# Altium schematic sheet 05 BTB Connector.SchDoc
size 594 x 420 mm
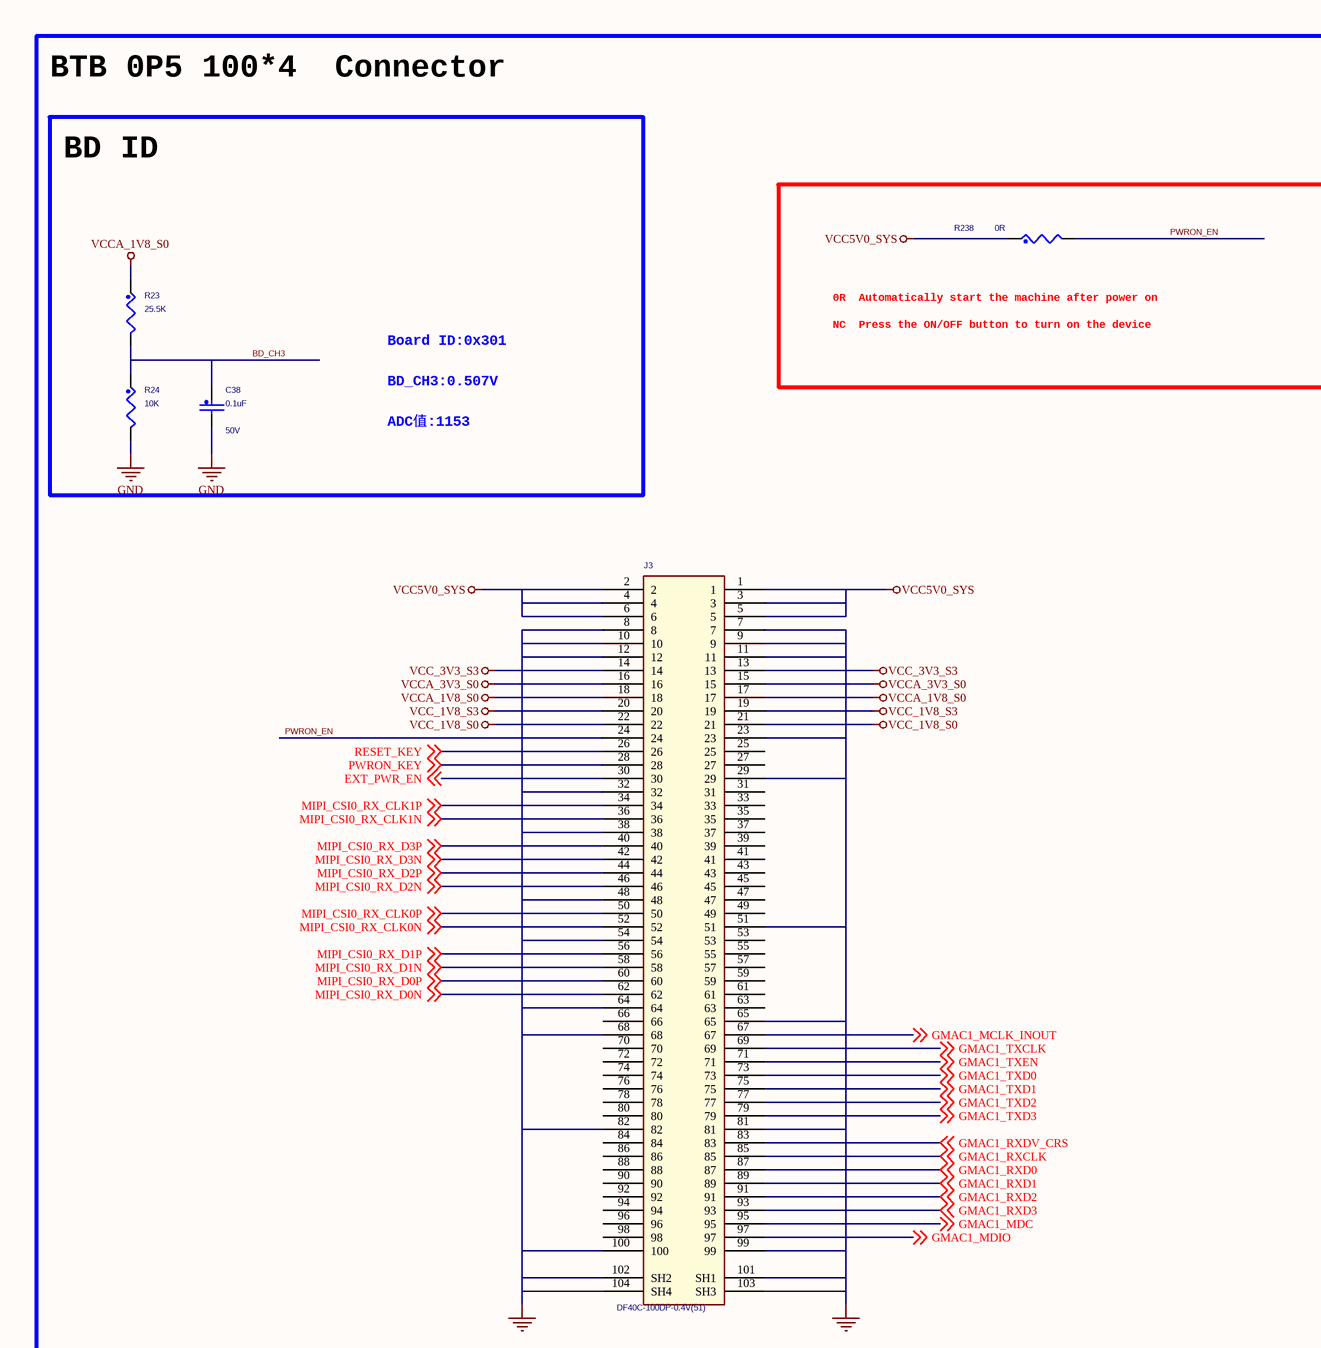
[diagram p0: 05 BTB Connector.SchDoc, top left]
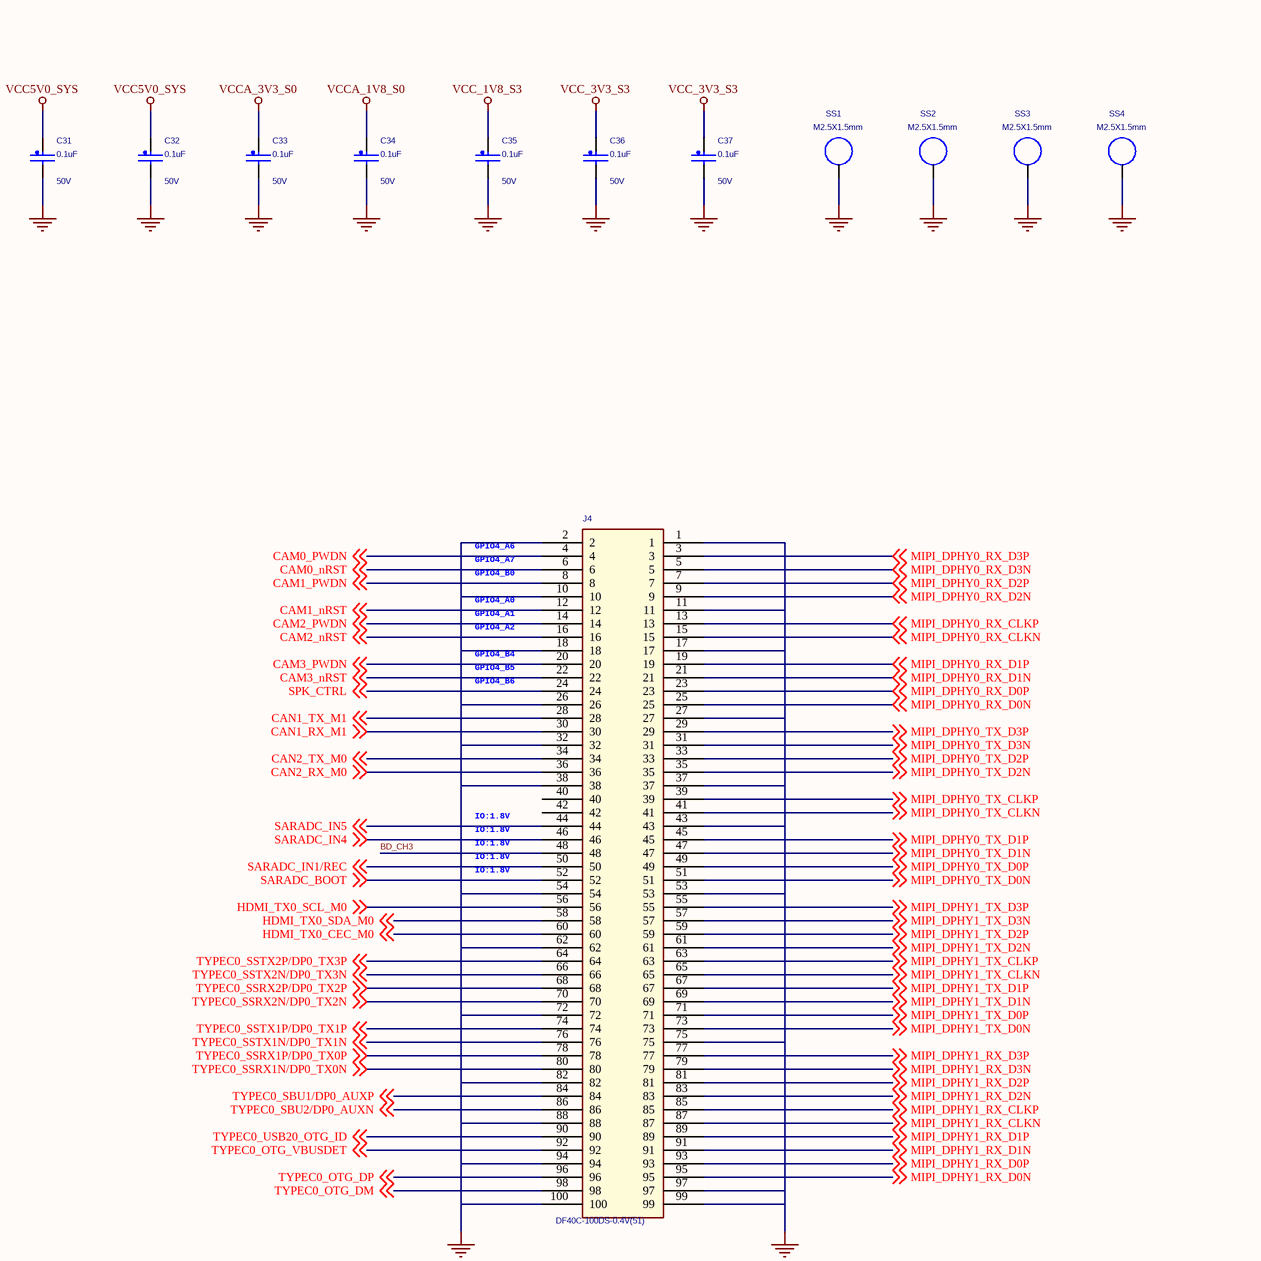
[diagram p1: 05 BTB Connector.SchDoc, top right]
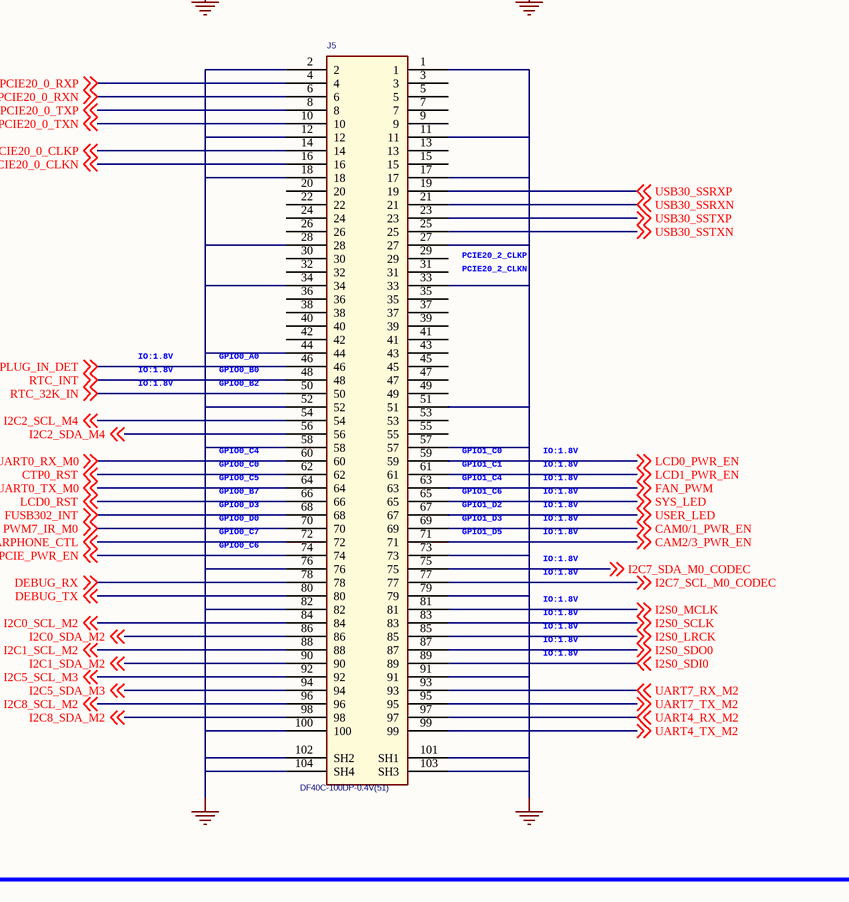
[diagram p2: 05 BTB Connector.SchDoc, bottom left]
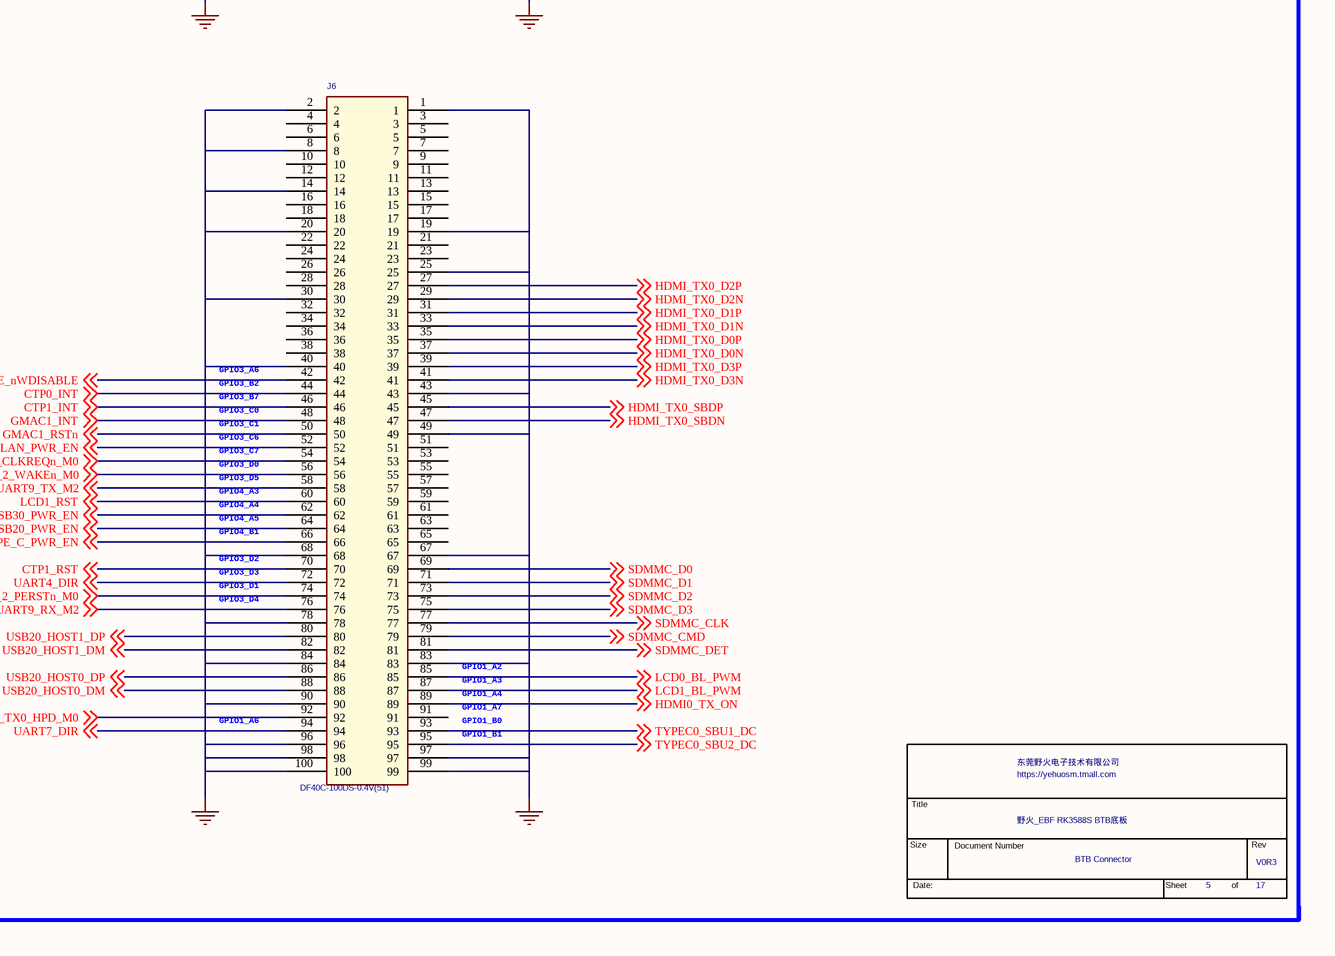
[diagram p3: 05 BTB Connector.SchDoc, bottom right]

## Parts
*  Page Count: 17  Page Number: 5  OrgName: 东莞野火电子技术有限公司  Title: 野火_EBF RK3588S BTB底板  RevCode: V0R3  Doc: BTB Connector  (hidden comment: TitleBlock_YHSCH)  (graphical)
C31  0.1uF  Voltage: 50V  [C0402]
C32  0.1uF  Voltage: 50V  [C0402]
C33  0.1uF  Voltage: 50V  [C0402]
C34  0.1uF  Voltage: 50V  [C0402]
C35  0.1uF  Voltage: 50V  [C0402]
C36  0.1uF  Voltage: 50V  [C0402]
C37  0.1uF  Voltage: 50V  [C0402]
C38  0.1uF  Voltage: 50V  [C0402]
J3  DF40C-100DP-0.4V(51)  [DF40C-100DP-0P4V]
J4  DF40C-100DS-0.4V(51)  [DF40HC-100DS-0P4V]
J5  DF40C-100DP-0.4V(51)  [DF40C-100DP-0P4V]
J6  DF40C-100DS-0.4V(51)  [DF40HC-100DS-0P4V]
R23  25.5K  [R0402]
R24  10K  [R0402]
R238  0R  [R0402]
SS1  M2.5X1.5mm  [SMTSO-M2r5]
SS2  M2.5X1.5mm  [SMTSO-M2r5]
SS3  M2.5X1.5mm  [SMTSO-M2r5]
SS4  M2.5X1.5mm  [SMTSO-M2r5]

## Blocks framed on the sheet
BD ID: C38 R23 R24

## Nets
GND: C31.2 C32.2 C33.2 C34.2 C35.2 C36.2 C37.2 C38.2 J3.7 J3.8 J3.9 J3.10 J3.11 J3.12 J3.23 J3.29 J3.32 J3.38 J3.48 J3.51 J3.54 J3.64 J3.65 J3.68 J3.81 J3.82 J3.99 J3.100 J3.101(SH1) J3.102(SH2) J3.103(SH3) J3.104(SH4) J4.1 J4.2 J4.10 J4.11 J4.17 J4.18 J4.26 J4.27 J4.32 J4.37 J4.38 J4.43 J4.53 J4.54 J4.62 J4.72 J4.75 J4.82 J4.88 J4.94 J4.97 J4.99 J4.100 J5.1 J5.2 J5.11 J5.12 J5.17 J5.18 J5.27 J5.28 J5.33 J5.34 J5.44 J5.51 J5.52 J5.57 J5.58 J5.73 J5.76 J5.79 J5.82 J5.91 J5.100 J5.101(SH1) J5.102(SH2) J5.103(SH3) J5.104(SH4) J6.1 J6.2 J6.8 J6.14 J6.19 J6.20 J6.25 J6.30 J6.40 J6.43 J6.49 J6.67 J6.68 J6.78 J6.83 J6.84 J6.90 J6.96 J6.97 J6.98 J6.99 J6.100 R24.2 SS1.1(NC_1) SS2.1(NC_1) SS3.1(NC_1) SS4.1(NC_1)
VCC5V0_SYS: C31.1 C32.1 J3.1 J3.2 J3.3 J3.4 J3.5 J3.6 R238.1
VCC_1V8_S0: J3.21 J3.22
VCC_1V8_S3: C35.1 J3.19 J3.20
VCC_3V3_S3: C36.1 C37.1 J3.13 J3.14
VCCA_1V8_S0: C34.1 J3.17 J3.18 R23.1
VCCA_3V3_S0: C33.1 J3.15 J3.16
BD_CH3: C38.1 J4.48 R23.2 R24.1
CAM0/1_PWR_EN: J5.69 ; off-sheet CAM0/1_PWR_EN
CAM0_nRST: J4.6 ; off-sheet CAM0_nRST
CAM0_PWDN: J4.4 ; off-sheet CAM0_PWDN
CAM1_nRST: J4.12 ; off-sheet CAM1_nRST
CAM1_PWDN: J4.8 ; off-sheet CAM1_PWDN
CAM2/3_PWR_EN: J5.71 ; off-sheet CAM2/3_PWR_EN
CAM2_nRST: J4.16 ; off-sheet CAM2_nRST
CAM2_PWDN: J4.14 ; off-sheet CAM2_PWDN
CAM3_nRST: J4.22 ; off-sheet CAM3_nRST
CAM3_PWDN: J4.20 ; off-sheet CAM3_PWDN
CAN1_RX_M1: J4.30 ; off-sheet CAN1_RX_M1
CAN1_TX_M1: J4.28 ; off-sheet CAN1_TX_M1
CAN2_RX_M0: J4.36 ; off-sheet CAN2_RX_M0
CAN2_TX_M0: J4.34 ; off-sheet CAN2_TX_M0
CTP0_INT: J6.44 ; off-sheet CTP0_INT
CTP0_RST: J5.62 ; off-sheet CTP0_RST
CTP1_INT: J6.46 ; off-sheet CTP1_INT
CTP1_RST: J6.70 ; off-sheet CTP1_RST
DEBUG_RX: J5.78 ; off-sheet DEBUG_RX
DEBUG_TX: J5.80 ; off-sheet DEBUG_TX
EARPHONE_CTL: J5.72 ; off-sheet EARPHONE_CTL
EXT_PWR_EN: J3.30 ; off-sheet EXT_PWR_EN
FAN_PWM: J5.63 ; off-sheet FAN_PWM
FUSB302_INT: J5.68 ; off-sheet FUSB302_INT
GMAC1_INT: J6.48 ; off-sheet GMAC1_INT
GMAC1_MCLK_INOUT: J3.67 ; off-sheet GMAC1_MCLK_INOUT
GMAC1_MDC: J3.95 ; off-sheet GMAC1_MDC
GMAC1_MDIO: J3.97 ; off-sheet GMAC1_MDIO
GMAC1_RSTn: J6.50 ; off-sheet GMAC1_RSTn
GMAC1_RXCLK: J3.85 ; off-sheet GMAC1_RXCLK
GMAC1_RXD0: J3.87 ; off-sheet GMAC1_RXD0
GMAC1_RXD1: J3.89 ; off-sheet GMAC1_RXD1
GMAC1_RXD2: J3.91 ; off-sheet GMAC1_RXD2
GMAC1_RXD3: J3.93 ; off-sheet GMAC1_RXD3
GMAC1_RXDV_CRS: J3.83 ; off-sheet GMAC1_RXDV_CRS
GMAC1_TXCLK: J3.69 ; off-sheet GMAC1_TXCLK
GMAC1_TXD0: J3.73 ; off-sheet GMAC1_TXD0
GMAC1_TXD1: J3.75 ; off-sheet GMAC1_TXD1
GMAC1_TXD2: J3.77 ; off-sheet GMAC1_TXD2
GMAC1_TXD3: J3.79 ; off-sheet GMAC1_TXD3
GMAC1_TXEN: J3.71 ; off-sheet GMAC1_TXEN
HDMI0_TX_ON: J6.89 ; off-sheet HDMI0_TX_ON
HDMI_TX0_CEC_M0: J4.60 ; off-sheet HDMI_TX0_CEC_M0
HDMI_TX0_D0N: J6.37 ; off-sheet HDMI_TX0_D0N
HDMI_TX0_D0P: J6.35 ; off-sheet HDMI_TX0_D0P
HDMI_TX0_D1N: J6.33 ; off-sheet HDMI_TX0_D1N
HDMI_TX0_D1P: J6.31 ; off-sheet HDMI_TX0_D1P
HDMI_TX0_D2N: J6.29 ; off-sheet HDMI_TX0_D2N
HDMI_TX0_D2P: J6.27 ; off-sheet HDMI_TX0_D2P
HDMI_TX0_D3N: J6.41 ; off-sheet HDMI_TX0_D3N
HDMI_TX0_D3P: J6.39 ; off-sheet HDMI_TX0_D3P
HDMI_TX0_HPD_M0: J6.92 ; off-sheet HDMI_TX0_HPD_M0
HDMI_TX0_SBDN: J6.47 ; off-sheet HDMI_TX0_SBDN
HDMI_TX0_SBDP: J6.45 ; off-sheet HDMI_TX0_SBDP
HDMI_TX0_SCL_M0: J4.56 ; off-sheet HDMI_TX0_SCL_M0
HDMI_TX0_SDA_M0: J4.58 ; off-sheet HDMI_TX0_SDA_M0
HP_PLUG_IN_DET: J5.46 ; off-sheet HP_PLUG_IN_DET
I2C0_SCL_M2: J5.84 ; off-sheet I2C0_SCL_M2
I2C0_SDA_M2: J5.86 ; off-sheet I2C0_SDA_M2
I2C1_SCL_M2: J5.88 ; off-sheet I2C1_SCL_M2
I2C1_SDA_M2: J5.90 ; off-sheet I2C1_SDA_M2
I2C2_SCL_M4: J5.54 ; off-sheet I2C2_SCL_M4
I2C2_SDA_M4: J5.56 ; off-sheet I2C2_SDA_M4
I2C5_SCL_M3: J5.92 ; off-sheet I2C5_SCL_M3
I2C5_SDA_M3: J5.94 ; off-sheet I2C5_SDA_M3
I2C7_SCL_M0_CODEC: J5.77 ; off-sheet I2C7_SCL_M0_CODEC
I2C7_SDA_M0_CODEC: J5.75 ; off-sheet I2C7_SDA_M0_CODEC
I2C8_SCL_M2: J5.96 ; off-sheet I2C8_SCL_M2
I2C8_SDA_M2: J5.98 ; off-sheet I2C8_SDA_M2
I2S0_LRCK: J5.85 ; off-sheet I2S0_LRCK
I2S0_MCLK: J5.81 ; off-sheet I2S0_MCLK
I2S0_SCLK: J5.83 ; off-sheet I2S0_SCLK
I2S0_SDI0: J5.89 ; off-sheet I2S0_SDI0
I2S0_SDO0: J5.87 ; off-sheet I2S0_SDO0
LCD0_BL_PWM: J6.85 ; off-sheet LCD0_BL_PWM
LCD0_PWR_EN: J5.59 ; off-sheet LCD0_PWR_EN
LCD0_RST: J5.66 ; off-sheet LCD0_RST
LCD1_BL_PWM: J6.87 ; off-sheet LCD1_BL_PWM
LCD1_PWR_EN: J5.61 ; off-sheet LCD1_PWR_EN
LCD1_RST: J6.60 ; off-sheet LCD1_RST
MINIPCIE_nWDISABLE: J6.42 ; off-sheet MINIPCIE_nWDISABLE
MINIPCIE_PWR_EN: J5.74 ; off-sheet MINIPCIE_PWR_EN
MIPI_CSI0_RX_CLK0N: J3.52 ; off-sheet MIPI_CSI0_RX_CLK0N
MIPI_CSI0_RX_CLK0P: J3.50 ; off-sheet MIPI_CSI0_RX_CLK0P
MIPI_CSI0_RX_CLK1N: J3.36 ; off-sheet MIPI_CSI0_RX_CLK1N
MIPI_CSI0_RX_CLK1P: J3.34 ; off-sheet MIPI_CSI0_RX_CLK1P
MIPI_CSI0_RX_D0N: J3.62 ; off-sheet MIPI_CSI0_RX_D0N
MIPI_CSI0_RX_D0P: J3.60 ; off-sheet MIPI_CSI0_RX_D0P
MIPI_CSI0_RX_D1N: J3.58 ; off-sheet MIPI_CSI0_RX_D1N
MIPI_CSI0_RX_D1P: J3.56 ; off-sheet MIPI_CSI0_RX_D1P
MIPI_CSI0_RX_D2N: J3.46 ; off-sheet MIPI_CSI0_RX_D2N
MIPI_CSI0_RX_D2P: J3.44 ; off-sheet MIPI_CSI0_RX_D2P
MIPI_CSI0_RX_D3N: J3.42 ; off-sheet MIPI_CSI0_RX_D3N
MIPI_CSI0_RX_D3P: J3.40 ; off-sheet MIPI_CSI0_RX_D3P
MIPI_DPHY0_RX_CLKN: J4.15 ; off-sheet MIPI_DPHY0_RX_CLKN
MIPI_DPHY0_RX_CLKP: J4.13 ; off-sheet MIPI_DPHY0_RX_CLKP
MIPI_DPHY0_RX_D0N: J4.25 ; off-sheet MIPI_DPHY0_RX_D0N
MIPI_DPHY0_RX_D0P: J4.23 ; off-sheet MIPI_DPHY0_RX_D0P
MIPI_DPHY0_RX_D1N: J4.21 ; off-sheet MIPI_DPHY0_RX_D1N
MIPI_DPHY0_RX_D1P: J4.19 ; off-sheet MIPI_DPHY0_RX_D1P
MIPI_DPHY0_RX_D2N: J4.9 ; off-sheet MIPI_DPHY0_RX_D2N
MIPI_DPHY0_RX_D2P: J4.7 ; off-sheet MIPI_DPHY0_RX_D2P
MIPI_DPHY0_RX_D3N: J4.5 ; off-sheet MIPI_DPHY0_RX_D3N
MIPI_DPHY0_RX_D3P: J4.3 ; off-sheet MIPI_DPHY0_RX_D3P
MIPI_DPHY0_TX_CLKN: J4.41 ; off-sheet MIPI_DPHY0_TX_CLKN
MIPI_DPHY0_TX_CLKP: J4.39 ; off-sheet MIPI_DPHY0_TX_CLKP
MIPI_DPHY0_TX_D0N: J4.51 ; off-sheet MIPI_DPHY0_TX_D0N
MIPI_DPHY0_TX_D0P: J4.49 ; off-sheet MIPI_DPHY0_TX_D0P
MIPI_DPHY0_TX_D1N: J4.47 ; off-sheet MIPI_DPHY0_TX_D1N
MIPI_DPHY0_TX_D1P: J4.45 ; off-sheet MIPI_DPHY0_TX_D1P
MIPI_DPHY0_TX_D2N: J4.35 ; off-sheet MIPI_DPHY0_TX_D2N
MIPI_DPHY0_TX_D2P: J4.33 ; off-sheet MIPI_DPHY0_TX_D2P
MIPI_DPHY0_TX_D3N: J4.31 ; off-sheet MIPI_DPHY0_TX_D3N
MIPI_DPHY0_TX_D3P: J4.29 ; off-sheet MIPI_DPHY0_TX_D3P
MIPI_DPHY1_RX_CLKN: J4.87 ; off-sheet MIPI_DPHY1_RX_CLKN
MIPI_DPHY1_RX_CLKP: J4.85 ; off-sheet MIPI_DPHY1_RX_CLKP
MIPI_DPHY1_RX_D0N: J4.95 ; off-sheet MIPI_DPHY1_RX_D0N
MIPI_DPHY1_RX_D0P: J4.93 ; off-sheet MIPI_DPHY1_RX_D0P
MIPI_DPHY1_RX_D1N: J4.91 ; off-sheet MIPI_DPHY1_RX_D1N
MIPI_DPHY1_RX_D1P: J4.89 ; off-sheet MIPI_DPHY1_RX_D1P
MIPI_DPHY1_RX_D2N: J4.83 ; off-sheet MIPI_DPHY1_RX_D2N
MIPI_DPHY1_RX_D2P: J4.81 ; off-sheet MIPI_DPHY1_RX_D2P
MIPI_DPHY1_RX_D3N: J4.79 ; off-sheet MIPI_DPHY1_RX_D3N
MIPI_DPHY1_RX_D3P: J4.77 ; off-sheet MIPI_DPHY1_RX_D3P
MIPI_DPHY1_TX_CLKN: J4.65 ; off-sheet MIPI_DPHY1_TX_CLKN
MIPI_DPHY1_TX_CLKP: J4.63 ; off-sheet MIPI_DPHY1_TX_CLKP
MIPI_DPHY1_TX_D0N: J4.73 ; off-sheet MIPI_DPHY1_TX_D0N
MIPI_DPHY1_TX_D0P: J4.71 ; off-sheet MIPI_DPHY1_TX_D0P
MIPI_DPHY1_TX_D1N: J4.69 ; off-sheet MIPI_DPHY1_TX_D1N
MIPI_DPHY1_TX_D1P: J4.67 ; off-sheet MIPI_DPHY1_TX_D1P
MIPI_DPHY1_TX_D2N: J4.61 ; off-sheet MIPI_DPHY1_TX_D2N
MIPI_DPHY1_TX_D2P: J4.59 ; off-sheet MIPI_DPHY1_TX_D2P
MIPI_DPHY1_TX_D3N: J4.57 ; off-sheet MIPI_DPHY1_TX_D3N
MIPI_DPHY1_TX_D3P: J4.55 ; off-sheet MIPI_DPHY1_TX_D3P
PCIE20_0_CLKN: J5.16 ; off-sheet PCIE20_0_CLKN
PCIE20_0_CLKP: J5.14 ; off-sheet PCIE20_0_CLKP
PCIE20_0_RXN: J5.6 ; off-sheet PCIE20_0_RXN
PCIE20_0_RXP: J5.4 ; off-sheet PCIE20_0_RXP
PCIE20_0_TXN: J5.10 ; off-sheet PCIE20_0_TXN
PCIE20_0_TXP: J5.8 ; off-sheet PCIE20_0_TXP
PCIE20x1_2_CLKREQn_M0: J6.54 ; off-sheet PCIE20x1_2_CLKREQn_M0
PCIE20x1_2_PERSTn_M0: J6.74 ; off-sheet PCIE20x1_2_PERSTn_M0
PCIE20x1_2_WAKEn_M0: J6.56 ; off-sheet PCIE20x1_2_WAKEn_M0
PWM7_IR_M0: J5.70 ; off-sheet PWM7_IR_M0
PWRON_EN: J3.24 R238.2
PWRON_KEY: J3.28 ; off-sheet PWRON_KEY
RESET_KEY: J3.26 ; off-sheet RESET_KEY
RTC_32K_IN: J5.50 ; off-sheet RTC_32K_IN
RTC_INT: J5.48 ; off-sheet RTC_INT
SARADC_BOOT: J4.52 ; off-sheet SARADC_BOOT
SARADC_IN1/REC: J4.50 ; off-sheet SARADC_IN1/REC
SARADC_IN4: J4.46 ; off-sheet SARADC_IN4
SARADC_IN5: J4.44 ; off-sheet SARADC_IN5
SDMMC_CLK: J6.77 ; off-sheet SDMMC_CLK
SDMMC_CMD: J6.79 ; off-sheet SDMMC_CMD
SDMMC_D0: J6.69 ; off-sheet SDMMC_D0
SDMMC_D1: J6.71 ; off-sheet SDMMC_D1
SDMMC_D2: J6.73 ; off-sheet SDMMC_D2
SDMMC_D3: J6.75 ; off-sheet SDMMC_D3
SDMMC_DET: J6.81 ; off-sheet SDMMC_DET
SPK_CTRL: J4.24 ; off-sheet SPK_CTRL
SYS_LED: J5.65 ; off-sheet SYS_LED
TYPE_C_PWR_EN: J6.66 ; off-sheet TYPE_C_PWR_EN
TYPEC0_OTG_DM: J4.98 ; off-sheet TYPEC0_OTG_DM
TYPEC0_OTG_DP: J4.96 ; off-sheet TYPEC0_OTG_DP
TYPEC0_OTG_VBUSDET: J4.92 ; off-sheet TYPEC0_OTG_VBUSDET
TYPEC0_SBU1/DP0_AUXP: J4.84 ; off-sheet TYPEC0_SBU1/DP0_AUXP
TYPEC0_SBU1_DC: J6.93 ; off-sheet TYPEC0_SBU1_DC
TYPEC0_SBU2/DP0_AUXN: J4.86 ; off-sheet TYPEC0_SBU2/DP0_AUXN
TYPEC0_SBU2_DC: J6.95 ; off-sheet TYPEC0_SBU2_DC
TYPEC0_SSRX1N/DP0_TX0N: J4.80 ; off-sheet TYPEC0_SSRX1N/DP0_TX0N
TYPEC0_SSRX1P/DP0_TX0P: J4.78 ; off-sheet TYPEC0_SSRX1P/DP0_TX0P
TYPEC0_SSRX2N/DP0_TX2N: J4.70 ; off-sheet TYPEC0_SSRX2N/DP0_TX2N
TYPEC0_SSRX2P/DP0_TX2P: J4.68 ; off-sheet TYPEC0_SSRX2P/DP0_TX2P
TYPEC0_SSTX1N/DP0_TX1N: J4.76 ; off-sheet TYPEC0_SSTX1N/DP0_TX1N
TYPEC0_SSTX1P/DP0_TX1P: J4.74 ; off-sheet TYPEC0_SSTX1P/DP0_TX1P
TYPEC0_SSTX2N/DP0_TX3N: J4.66 ; off-sheet TYPEC0_SSTX2N/DP0_TX3N
TYPEC0_SSTX2P/DP0_TX3P: J4.64 ; off-sheet TYPEC0_SSTX2P/DP0_TX3P
TYPEC0_USB20_OTG_ID: J4.90 ; off-sheet TYPEC0_USB20_OTG_ID
UART0_RX_M0: J5.60 ; off-sheet UART0_RX_M0
UART0_TX_M0: J5.64 ; off-sheet UART0_TX_M0
UART4_DIR: J6.72 ; off-sheet UART4_DIR
UART4_RX_M2: J5.97 ; off-sheet UART4_RX_M2
UART4_TX_M2: J5.99 ; off-sheet UART4_TX_M2
UART7_DIR: J6.94 ; off-sheet UART7_DIR
UART7_RX_M2: J5.93 ; off-sheet UART7_RX_M2
UART7_TX_M2: J5.95 ; off-sheet UART7_TX_M2
UART9_RX_M2: J6.76 ; off-sheet UART9_RX_M2
UART9_TX_M2: J6.58 ; off-sheet UART9_TX_M2
USB20_HOST0_DM: J6.88 ; off-sheet USB20_HOST0_DM
USB20_HOST0_DP: J6.86 ; off-sheet USB20_HOST0_DP
USB20_HOST1_DM: J6.82 ; off-sheet USB20_HOST1_DM
USB20_HOST1_DP: J6.80 ; off-sheet USB20_HOST1_DP
USB20_PWR_EN: J6.64 ; off-sheet USB20_PWR_EN
USB30_PWR_EN: J6.62 ; off-sheet USB30_PWR_EN
USB30_SSRXN: J5.21 ; off-sheet USB30_SSRXN
USB30_SSRXP: J5.19 ; off-sheet USB30_SSRXP
USB30_SSTXN: J5.25 ; off-sheet USB30_SSTXN
USB30_SSTXP: J5.23 ; off-sheet USB30_SSTXP
USER_LED: J5.67 ; off-sheet USER_LED
WLAN_PWR_EN: J6.52 ; off-sheet WLAN_PWR_EN

Not connected (* = marked no-connect by the designer): J3 25 27 31 33 35 37 39 41 43 45 47 49 53 55 57 59 61 63 66 70 72 74 76 78 80 84 86 88 90 92 94 96 98; J4 40 42; J5 3 5 7 9 13 15 20 22 24 26 29 30 31 32 35 36 37 38 39 40 41 42 43 45 47 49 53 55; J6 3 4 5 6 7 9 10 11 12 13 15 16 17 18 21 22 23 24 26 28 32 34 36 38 51 53 55 57 59 61 63 65 91

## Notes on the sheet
- BTB 0P5 100*4  Connector
- Board ID:0x301
- 0R  Automatically start the machine after power on
- NC  Press the ON/OFF button to turn on the device
- BD_CH3:0.507V
- ADC值:1153
- GPIO4_A6
- GPIO4_A7
- GPIO4_B0
- GPIO4_A0
- GPIO4_A1
- GPIO4_A2
- GPIO4_B4
- GPIO4_B5
- GPIO4_B6
- IO:1.8V
- PCIE20_2_CLKP
- PCIE20_2_CLKN
- GPIO0_A0
- GPIO0_B0
- GPIO0_B2
- GPIO3_A6
- GPIO3_B2
- GPIO3_B7
- GPIO3_C1
- GPIO3_C0
- GPIO0_C4
- GPIO1_C0
- GPIO3_C6
- GPIO3_D5
- GPIO4_A3
- GPIO3_C7
- GPIO3_D0
- GPIO0_D3
- GPIO0_D0
- GPIO0_C5
- GPIO0_C0
- GPIO0_B7
- GPIO1_C1
- GPIO1_C4
- GPIO1_C6
- GPIO1_D2
- GPIO1_D3
- GPIO4_A4
- GPIO4_A5
- GPIO3_D2
- GPIO4_B1
- GPIO0_C7
- GPIO0_C6
- GPIO1_D5
- GPIO3_D3
- GPIO3_D4
- GPIO3_D1
- GPIO1_A2
- GPIO1_A3
- GPIO1_A4
- GPIO1_A6
- GPIO1_A7
- GPIO1_B0
- GPIO1_B1

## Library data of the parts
* = TitleBlock_YHSCH: Cage Code: 1
C31-C34 C36 = CAP_NP_Dup1: CLASS: DISCRETE; 规格: 贴片电容0.1uF 10% 50V X5R 0402; 规格编号: 0402X104K500NT; 条码: EBF29060118; 品牌: 风华; 类别: 贴片电容0402; 规格书: 风华电容.pdf; 价格: 0.029826; 生命周期: 量产
C35 C37 = CAP_NP_Dup1: CLASS: DISCRETE; 生命周期: 量产; 价格: 0.029826; 规格书: 风华电容.pdf; 类别: 贴片电容0402; 品牌: 风华; 条码: EBF29060118; 规格编号: 0402X104K500NT; 规格: 贴片电容0.1uF 10% 50V X5R 0402
C38 = CAP_NP: CLASS: DISCRETE; 生命周期: 量产; 价格: 0.029826; 规格书: 风华电容.pdf; 类别: 贴片电容0402; 品牌: 风华; 条码: EBF29060118; 规格编号: 0402X104K500NT; 规格: 贴片电容0.1uF 10% 50V X5R 0402
J3 = DF40C-100DP: 备注: 鲁班猫cm4; 生命周期: 量产; 价格: 3.39; 规格书: 广濑-DF40_Catalog.pdf; 类别: BTB连接器; 品牌: 广濑; 条码: EBFCIS231113172457; 规格: 0.4mm BTB公座2*50P 双槽 立贴式 高度1.14mm
J4 = SGDBM-05-100P-H10: 规格: 0.4mm BTB母座2*50P 双槽 立贴式 合高1.5mm; 条码: EBFCIS231113172912; 品牌: 广濑; 类别: BTB连接器; 规格书: 广濑-DF40_Catalog.pdf; 价格: 3.93; 生命周期: 量产; 备注: 鲁班猫cm4
J5 = DF40C-100DP: 规格: 0.4mm BTB公座2*50P 双槽 立贴式 高度1.14mm; 条码: EBFCIS231113172457; 品牌: 广濑; 类别: BTB连接器; 规格书: 广濑-DF40_Catalog.pdf; 价格: 3.39; 生命周期: 量产; 备注: 鲁班猫cm4
J6 = SGDBM-05-100P-H10: 备注: 鲁班猫cm4; 生命周期: 量产; 价格: 3.93; 规格书: 广濑-DF40_Catalog.pdf; 类别: BTB连接器; 品牌: 广濑; 条码: EBFCIS231113172912; 规格: 0.4mm BTB母座2*50P 双槽 立贴式 合高1.5mm
R23 = RES: CLASS: DISCRETE; 价格: 0.006152; 生命周期: 量产; 规格书: 厚声-无铅厚膜电阻.pdf; 类别: 贴片电阻0402; 品牌: 厚声; 条码: EBF29070291; 规格编号: CQ02WGF2552TCE; 规格: 贴片电阻25.5K 1% 1/16W 0402
R24 = RES: CLASS: DISCRETE; 规格: 贴片电阻10K 1% 1/16W 0402; 条码: EBF29070046; 类别: 贴片电阻0402; 规格编号: 0402WGF1002TCE; 品牌: 厚声; 规格书: 厚声-无铅厚膜电阻.pdf; 价格: 0.002773; 生命周期: 量产
R238 = RES: CLASS: DISCRETE; 生命周期: 量产; 规格书: 合科泰-RI系列电阻.pdf; 类别: 贴片电阻0402; 品牌: 合科泰; 条码: EBF29070049; 规格编号: RI0402L000FT; 规格: 贴片电阻0R 1% 1/16W 0402
SS1 SS3 = SPACER: CLASS: IC; 规格: SMT贴片螺母M2.5 台阶高度1.4MM 台阶外径：4.09MM 螺柱长度：1.5MM; 规格编号: SMTSO2515CTJ; 条码: EBFCIS240816170946; 品牌: 雄和远景; 类别: 贴片螺母; 规格书: 雄和远景_SMTSO2530CTJ.pdf; 生命周期: 量产; 备注: 通用
SS2 SS4 = SPACER: CLASS: IC; 备注: 通用; 生命周期: 量产; 规格书: 雄和远景_SMTSO2530CTJ.pdf; 类别: 贴片螺母; 品牌: 雄和远景; 条码: EBFCIS240816170946; 规格编号: SMTSO2515CTJ; 规格: SMT贴片螺母M2.5 台阶高度1.4MM 台阶外径：4.09MM 螺柱长度：1.5MM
